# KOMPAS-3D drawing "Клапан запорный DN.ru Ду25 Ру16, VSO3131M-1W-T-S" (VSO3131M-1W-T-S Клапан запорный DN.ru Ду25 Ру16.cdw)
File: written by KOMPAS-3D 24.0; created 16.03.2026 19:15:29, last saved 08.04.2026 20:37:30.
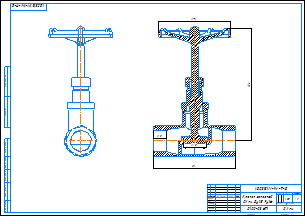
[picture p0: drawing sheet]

Document properties: c3d_UniqueCompID: 94d3474e-3e6e-4ddd-ad0b-ef51eb5e31da; Обозначение: VSO3131M-1W-T-S; Наименование: Клапан запорный DN.ru Ду25 Ру16; Материал: Сталь 10 ГОСТ 1050-2013; Автор: artiomk228874@gmail.com; Класс точности: c; Знак неуказанной шероховатости: Шероховатость не задана; Рассекать на разрезах: Да; Автор: artiomk228874@gmail.com; Форматы листов документа: A2; Полное имя файла: VSO3131M-1W-T-S Клапан запорный DN.ru Ду25 Ру16.m3d; Масса: 0.55; Наименование: Клапан запорный DN.ru Ду25 Ру16; Количество листов документа: 1; Примечание: D100-03671

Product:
- Body: Тело 1  | qty 1
    Масса: 0.324398
- Part/product: Клапан запорный DN.ru Ду25 Ру16  | designation VSO3131M-1W-T-S
    Масса: 0.55
    Раздел спецификации: Прочие изделия
    Форматы листов документа: A2
    Примечание: D100-03671
    additional columns: 94d3474e-3e6e-4ddd-ad0b-ef51eb5e31da; VSO3131M-1W-T-S; Сталь 10 ГОСТ 1050-2013; artiomk228874@gmail.com; c; Шероховатость не задана; Да

Views: Проекционный вид 2
Referenced files in C:\Users\artio\OneDrive\Рабочий стол\Клапан запорный DN.ru VSO3131M-1W-T-S Ду15-Ду50 Ру16\Ду25\: VSO3131M-1W-T-S Клапан запорный DN.ru Ду25 Ру16.m3d, VSO3131M-1W-T-S Клапан запорный DN.ru Ду25 Ру16.cdw
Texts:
  VSO3131M-1W-T-S
  Клапан запорный
  DN.ru Ду25 Ру16
  Клапан запорный DN.ru Ду25 Ру16
  VSO3131M-1W-T-S Клапан запорный DN.ru Ду25 Ру16
Dimensions and other numbers on the sheet: 0; 3; 4; 2:1; 1; 2; 0,55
